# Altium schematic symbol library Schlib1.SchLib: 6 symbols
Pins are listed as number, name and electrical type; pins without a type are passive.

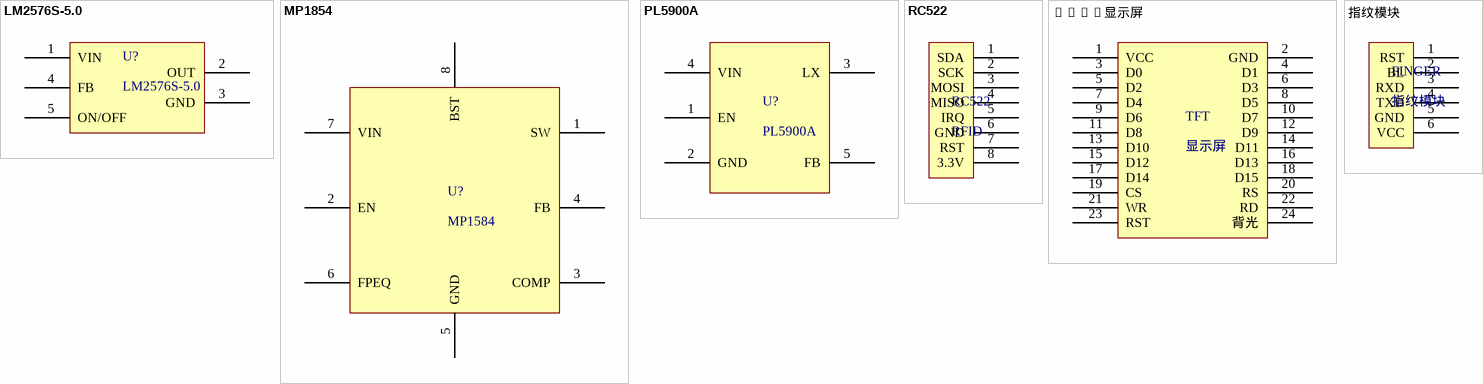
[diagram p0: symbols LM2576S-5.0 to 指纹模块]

## LM2576S-5.0
designator U?
footprint TO263-5A (263，5脚晶体管)
pins: 1 VIN, 2 OUT, 3 GND, 4 FB, 5 ON/OFF

## MP1854
designator U?, comment MP1584
footprint SOP8_L (5*6*1.8mm（长宽高）)
pins: 1 SW, 2 EN, 3 COMP, 4 FB, 5 GND, 6 FPEQ, 7 VIN, 8 BST

## PL5900A
designator U?
footprint SOT23-5L (3x1.6x1.1mm(长宽高))
pins: 1 EN, 2 GND, 3 LX, 4 VIN, 5 FB

## RC522
designator RC522, comment RFID
footprint HDR2.54-LI-8P (排针，8脚)
pins: 1 SDA, 2 SCK, 3 MOSI, 4 MISO, 5 IRQ, 6 GND, 7 RST, 8 3.3V

## TFFT显示屏
designator TFT, comment 显示屏
footprint HDR2.54-LI-2x12P (双排排针，12x2脚)
pins: 1 VCC, 2 GND, 3 D0, 4 D1, 5 D2, 6 D3, 7 D4, 8 D5, 9 D6, 10 D7, 11 D8, 12 D9, 13 D10, 14 D11, 15 D12, 16 D13, 17 D14, 18 D15, 19 CS, 20 RS, 21 WR, 22 RD, 23 RST, 24 背光

## 指纹模块
designator FINGER
footprint HDR2.54-LI-6P (排针，6脚)
pins: 1 RST, 2 BL, 3 RXD, 4 TXD, 5 GND, 6 VCC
